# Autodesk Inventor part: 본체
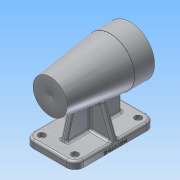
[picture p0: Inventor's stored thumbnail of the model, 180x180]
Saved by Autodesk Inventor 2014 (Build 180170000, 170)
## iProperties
Created: 2018-09
Part Number: 본체
Material: 알루미늄 6061
Document SubType Name: Modeling
Designer: Administrator
Density: 2.71 g/cm^3
Appearance: 알루미늄 - 평지
Mass: 703.596 g
Surface Area: 701.76 cm^2
Volume: 259.63 cm^3
Author: Administrator
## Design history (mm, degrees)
revolve "회전1" stored, may be unused: angle "d7" = 90 deg
sketch "스케치3"
  geometry: L1 (0, 0)-(0, 112); L2 (0, 112)-(-21, 112); L3 (-21, 112)-(-21, 97); L4 (-21, 97)-(-24, 97); L5 (-24, 97)-(-24, 43); L6 (-24, 43)-(-18, 43); L7 (-18, 43)-(-18, 31); L8 (-18, 31)-(-14.5, 31); L9 (-14.5, 31)-(-14.5, 13); L10 (-14.5, 13)-(-13, 13); L11 (-13, 13)-(-13, 9); L12 (-13, 9)-(-7.5, 9); L13 (-7.5, 9)-(-7.5, 6); L14 (-7.5, 6)-(0, 6)
  constraints: 28 end point, 10 parallel, 3 perpendicular, 1 point on line, 1 vertical
  dimensions: "d8" = 112 distance of L1.start L1.end; "d9" = 21 distance of L1.end L2.end; "d10" = 15 distance of L2.end L3.end; "d11" = 3 distance of L3.end L4.end; "d12" = 54 distance of L4.end L5.end; "d13" = 6 distance of L5.end L6.end; "d14" = 12 distance of L6.end L7.end; "d15" = 3.5 distance of L7.end L8.end; "d16" = 18 distance of L8.end L9.end; "d17" = 1.5 distance of L9.end L10.end; "d18" = 4 distance of L10.end L11.end; "d19" = 5.5 distance of L11.end L12.end; "d20" = 3 distance of L12.end L13.end
revolve "회전2" sketch "스케치3" stored, may be unused: angle "d21" = 90 deg
node "작업 평면1"
sketch "스케치4"
  geometry: L1 (0, 35)-(112, 35); L2 (112, 35)-(112, -35); L3 (112, -35)-(0, -35); L4 (0, -35)-(0, 35); 2 further points
  constraints: 8 end point, 2 parallel, 1 coincident, 1 horizontal, 1 midpoint, 1 perpendicular
  dimensions: "d23" = 112 distance of L2.end L3.end; "d24" = 70 distance of L1.end L2.end
extrude "돌출1" join sketch "스케치4" distance "d25" = 10; taper "d26" = 0 deg
node "작업 평면2"
sketch "스케치5"
  geometry: L1 (-64, 0)-(-64, 35); L2 (-64, 35)-(-21.714, 19.609); L3 (-29.258, 0)-(-64, 0); C1 r 26.301 at (0, 0) reference; C2 r 34 at (0, 0) reference; A1 r 29.258 centre (0, 0) between (-21.714, 19.609) and (-29.258, 0); 1 further point
  constraints: 6 end point, 2 point on circle, 1 centre point, 1 coincident, 1 perpendicular, 1 vertical
  dimensions: "d28" = 35 distance of L1.start L1.end; "d29" = 45 distance of L1.end L2.end; "d30" = 70 deg angle of L1 L2; "d31" = 64 distance of point (0, 0) L1.start; "d32" = 29.2576 radius of A1
extrude "돌출2" join sketch "스케치5" stored distance "d33" = 8; taper "d34" = 0 deg
node "작업 평면3"
fillet "모깎기2" dims "d47" = 3
fillet "모깎기3" dims "d48" = 3
fillet "모깎기4" dims "d49" = 12
fillet "모깎기5" dims "d50" = 3
sketch "스케치7"
  geometry: C1 r 4.75 at (-23, 12); C2 r 4.75 at (23, 12); A1 r 9 centre (23, 12) between (23, 3) and (32, 12) reference; A2 r 9 centre (-23, 12) between (-32, 12) and (-23, 3) reference; 1 further point
  constraints: 2 centre point, 2 coincident
  dimensions: "d51" = 9.5 diameter of C1; "d52" = 9.5 diameter of C2
extrude "돌출4" cut sketch "스케치7" distance "d53" = 5.4; taper "d54" = 0 deg
sketch "스케치8"
  geometry: C1 r 4.75 at (0, 0) reference; C2 r 2.75 at (0, 0); 1 further point
  constraints: 1 centre point, 1 coincident
  dimensions: "d55" = 5.5 diameter of C2
extrude "돌출5" cut sketch "스케치8" stored distance "d56" = 5.4; taper "d57" = 0 deg
sketch "스케치9"
  geometry: C1 r 4.75 at (0, 0) reference; C2 r 2.75 at (0, 0); 1 further point
  constraints: 1 centre point, 1 coincident
  dimensions: "d58" = 5.5 diameter of C2
extrude "돌출6" cut sketch "스케치9" stored distance "d59" = 5.4; taper "d60" = 0 deg
fillet "모깎기6" dims "d61" = 0.3
fillet "모깎기7" dims "d62" = 3
chamfer "모따기1" distance "d63" = 1; stored, may be unused: second distance "d64" = 2, angle "d65" = 45 deg
sketch "스케치10"
  geometry: L1 (74, -23)-(74, 23) reference; C1 r 34 at (0, 0) reference; 1 further point
  dimensions: "d66" = 26 distance of C1.centre point (0, 26); "d67" = 74 distance from line of L1 point (0, 26)
hole "구멍1" sketch "스케치10" at (0, 26) diameter "d68" = 3.242; stored, may be unused: countersink angle "d72" = 90 deg, drill point angle "d74" = 118 deg; dims "d69" = 8, "d70" = 4, "d71" = 2, "d73" = 11
node "작업 평면5"
sketch "스케치12"
  geometry: L1 (0, 0)-(0, 88) reference; L2 (0, 100)-(-7, 100) reference; 2 further points
  constraints: 1 other
  dimensions: "d78" = 3 distance from line of L1 point (-3, 44); "d79" = 56 distance from line of L2 point (-3, 44)
feature "엠보싱1" sketch "스케치12" dims "d8" = 112, "d9" = 21, "d10" = 15, "d11" = 3, "d12" = 54, "d13" = 6, "d14" = 12, "d15" = 3.5, "d16" = 18, "d17" = 1.5, "d18" = 4, "d19" = 5.5, "d20" = 3, "d80" = 0.5, "d81" = 0
sketch "스케치13"
  geometry: L1 (-50.241, 0.598)-(-97.759, 0.598) reference; L2 (-49.497, 52)-(-49.497, 52) reference; L3 (-48.541, 60)-(-48.541, 60) reference; L4 (-40.022, 83.818)-(-107.978, 83.818) reference; L5 (-40, 112)-(-108, 112) reference; L6 (-108, 84.183)-(-40, 84.183) reference; L7 (-50.241, 0.598)-(-40.022, 83.818) reference; L8 (-40, 84.183)-(-40, 112) reference; L9 (-10, 0)-(-10, 18); L10 (-10, 18)-(-48.637, 28.353); L11 (-10, 96)-(-40, 96); L12 (-10, 18)-(-10, 96); L13 (-46.89, 27.885)-(-40, 84.183); 5 further points
  constraints: 10 end point, 3 point on line, 1 perpendicular, 6 other
  dimensions: "d93" = 64 distance of point (-74, 0) L9.start; "d94" = 18 distance of L9.start L9.end; "d96" = 105 deg angle of L10 L9; "d98" = 96 vertical distance of point (-74, 0) L11.start; "d99" = 78 distance of L9.end L11.start; "d100" = 17.40247 distance from line of L1 L9.end; "d101" = 25.36297 horizontal distance of point (-74, 0) L10.end; "d102" = 38.63703 horizontal distance of L9.end L10.end
extrude "돌출7" join sketch "스케치13" stored distance "d103" = 8; taper "d104" = 0 deg
fillet "모깎기14" dims "d105" = 3
fillet "모깎기15" dims "d106" = 3
fillet "모깎기16" dims "d107" = 3
fillet "모깎기17" dims "d108" = 3
node "솔리드1"
mirror "대칭1"
mirror "대칭2"
mirror "대칭3"
pattern_circular "원형 패턴1" dims angle "d76" = 360 deg
sketch "스케치2"
  geometry: L1 (0, 0)-(112, 0); L2 (112, 0)-(112, 34); L3 (112, 34)-(84, 34); L4 (84, 34)-(184, 34); L5 (84, 34)-(0.598, 23.759); A1 r 80 centre (80, 14) between (0.598, 23.759) and (1.235, 0)
  constraints: 10 end point, 2 horizontal, 2 point on circle, 1 centre point, 1 parallel, 1 perpendicular, 1 point on line
  dimensions: "d0" = 112 distance of L1.start L1.end; "d1" = 34 distance of L1.end L2.end; "d2" = 28 distance of L2.end L3.end; "d91" = 7 deg angle of L3 L5; "d92" = 80 radius of A1
node "투영된 루프1"
node "투영된 루프3"
node "투영된 루프4"
other parameters: "d22" = 74, "d27" = 56, "d89" = 173 deg
